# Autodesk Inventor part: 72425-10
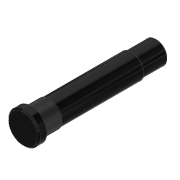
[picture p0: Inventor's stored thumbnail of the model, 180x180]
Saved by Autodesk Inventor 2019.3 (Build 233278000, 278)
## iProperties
Created: 2012-10
Part Number: 72425-10
Material: Ogólny
Document SubType Name: Modeling
Designer: CADENGINEERING4
Density: 1 g/cm^3
Appearance: Gładki — czarny
Author: CADENGINEERING4
Revision Number: ÈÎºÎ
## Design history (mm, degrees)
feature "ÊäÈë1"
node "Bryła1"
